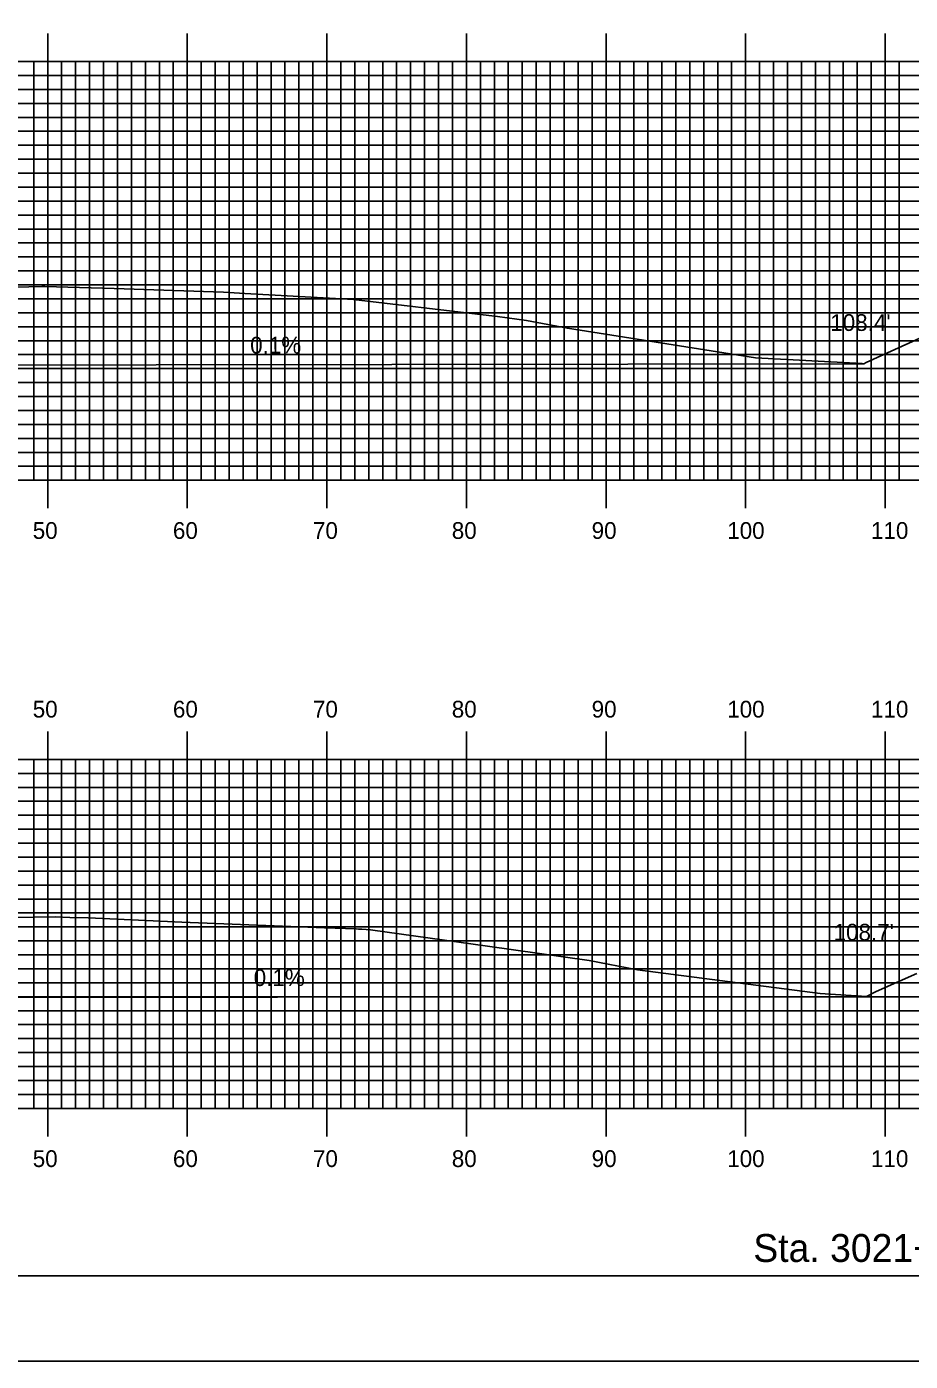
# Model space of a CAD drawing. Extents: x 1686373 to 1686716, y 461260 to 461480.
# Drawn here: x 1686587.3 to 1686650.6, y 461260 to 461355.6 of the extents above; entities that cross this region are included whole.
import ezdxf

# ---------------------------------------------------------------- set-up
doc = ezdxf.new("R2010")
doc.units = 0
for name, color, linetype in [('ANNOTATION', 7, 'Continuous'), ('BORDER', 7, 'Continuous'), ('D_Roadway_SlopeLines', 7, 'Continuous'), ('D_Text_Standard', 7, 'Continuous'), ('H_V ANNOTATION', 7, 'Continuous'), ('M_Roadway_Centerline', 7, 'Continuous'), ('MAJOR', 7, 'Continuous'), ('MINOR', 7, 'Continuous'), ('PLOT BOUNDARY', 7, 'Continuous'), ('S_Roadway_Centerline', 7, 'Continuous')]:
    doc.layers.add(name, color=color, linetype=linetype)

msp = doc.modelspace()

# ---------------------------------------------------------------- linework, layer by layer
at = {"layer": 'BORDER'}
msp.add_lwpolyline([(1686389.169, 461266.072), (1686709.169, 461266.072), (1686709.169, 461476.072), (1686389.169, 461476.072)], close=True, dxfattribs=at)
at = {"layer": 'D_Roadway_SlopeLines'}
for points in [[(1686562.725, 461331.296), (1686647.215, 461331.409)], [(1686562.725, 461331.296), (1686647.215, 461331.409)], [(1686562.725, 461331.296), (1686647.215, 461331.409)], [(1686562.725, 461331.296), (1686647.215, 461331.409)], [(1686563.024, 461285.988), (1686647.42, 461286.094)], [(1686563.024, 461285.988), (1686647.42, 461286.094)], [(1686563.024, 461285.988), (1686647.42, 461286.094)], [(1686563.024, 461285.988), (1686647.42, 461286.094)]]:
    msp.add_lwpolyline(points, dxfattribs=at)
at = {"layer": 'MAJOR'}
for p, q in [((1686588.769, 461355.076), (1686588.769, 461353.072)), ((1686598.769, 461355.076), (1686598.769, 461353.072)), ((1686608.769, 461355.076), (1686608.769, 461353.072)), ((1686618.769, 461355.076), (1686618.769, 461353.072)), ((1686628.769, 461355.076), (1686628.769, 461353.072)), ((1686638.769, 461355.076), (1686638.769, 461353.072)), ((1686648.769, 461355.076), (1686648.769, 461353.072)), ((1686398.769, 461353.072), (1686678.769, 461353.072)), ((1686398.769, 461353.072), (1686678.769, 461353.072)), ((1686588.769, 461323.072), (1686588.769, 461353.072)), ((1686598.769, 461323.072), (1686598.769, 461353.072)), ((1686608.769, 461323.072), (1686608.769, 461353.072)), ((1686618.769, 461323.072), (1686618.769, 461353.072)), ((1686628.769, 461323.072), (1686628.769, 461353.072)), ((1686638.769, 461323.072), (1686638.769, 461353.072)), ((1686648.769, 461323.072), (1686648.769, 461353.072)), ((1686398.769, 461348.072), (1686678.769, 461348.072)), ((1686398.769, 461343.072), (1686678.769, 461343.072)), ((1686398.769, 461338.072), (1686678.769, 461338.072)), ((1686398.769, 461333.072), (1686678.769, 461333.072)), ((1686398.769, 461328.072), (1686678.769, 461328.072)), ((1686398.769, 461323.072), (1686678.769, 461323.072)), ((1686398.769, 461323.072), (1686678.769, 461323.072)), ((1686588.769, 461321.068), (1686588.769, 461323.072)), ((1686598.769, 461321.068), (1686598.769, 461323.072)), ((1686608.769, 461321.068), (1686608.769, 461323.072)), ((1686618.769, 461321.068), (1686618.769, 461323.072)), ((1686628.769, 461321.068), (1686628.769, 461323.072)), ((1686638.769, 461321.068), (1686638.769, 461323.072)), ((1686648.769, 461321.068), (1686648.769, 461323.072)), ((1686588.769, 461305.076), (1686588.769, 461303.072)), ((1686598.769, 461305.076), (1686598.769, 461303.072)), ((1686608.769, 461305.076), (1686608.769, 461303.072)), ((1686618.769, 461305.076), (1686618.769, 461303.072)), ((1686628.769, 461305.076), (1686628.769, 461303.072)), ((1686638.769, 461305.076), (1686638.769, 461303.072)), ((1686648.769, 461305.076), (1686648.769, 461303.072)), ((1686398.769, 461303.072), (1686678.769, 461303.072)), ((1686398.769, 461303.072), (1686678.769, 461303.072)), ((1686588.769, 461278.072), (1686588.769, 461303.072)), ((1686598.769, 461278.072), (1686598.769, 461303.072)), ((1686608.769, 461278.072), (1686608.769, 461303.072)), ((1686618.769, 461278.072), (1686618.769, 461303.072)), ((1686628.769, 461278.072), (1686628.769, 461303.072)), ((1686638.769, 461278.072), (1686638.769, 461303.072)), ((1686648.769, 461278.072), (1686648.769, 461303.072)), ((1686398.769, 461298.072), (1686678.769, 461298.072)), ((1686398.769, 461293.072), (1686678.769, 461293.072)), ((1686398.769, 461288.072), (1686678.769, 461288.072)), ((1686398.769, 461283.072), (1686678.769, 461283.072)), ((1686398.769, 461278.072), (1686678.769, 461278.072)), ((1686398.769, 461278.072), (1686678.769, 461278.072)), ((1686588.769, 461276.068), (1686588.769, 461278.072)), ((1686598.769, 461276.068), (1686598.769, 461278.072)), ((1686608.769, 461276.068), (1686608.769, 461278.072)), ((1686618.769, 461276.068), (1686618.769, 461278.072)), ((1686628.769, 461276.068), (1686628.769, 461278.072)), ((1686638.769, 461276.068), (1686638.769, 461278.072)), ((1686648.769, 461276.068), (1686648.769, 461278.072))]:
    msp.add_line(p, q, dxfattribs=at)
at = {"layer": 'MINOR'}
for p, q in [((1686587.769, 461323.072), (1686587.769, 461353.072)), ((1686589.769, 461323.072), (1686589.769, 461353.072)), ((1686590.769, 461323.072), (1686590.769, 461353.072)), ((1686591.769, 461323.072), (1686591.769, 461353.072)), ((1686592.769, 461323.072), (1686592.769, 461353.072)), ((1686593.769, 461323.072), (1686593.769, 461353.072)), ((1686594.769, 461323.072), (1686594.769, 461353.072)), ((1686595.769, 461323.072), (1686595.769, 461353.072)), ((1686596.769, 461323.072), (1686596.769, 461353.072)), ((1686597.769, 461323.072), (1686597.769, 461353.072)), ((1686599.769, 461323.072), (1686599.769, 461353.072)), ((1686600.769, 461323.072), (1686600.769, 461353.072)), ((1686601.769, 461323.072), (1686601.769, 461353.072)), ((1686602.769, 461323.072), (1686602.769, 461353.072)), ((1686603.769, 461323.072), (1686603.769, 461353.072)), ((1686604.769, 461323.072), (1686604.769, 461353.072)), ((1686605.769, 461323.072), (1686605.769, 461353.072)), ((1686606.769, 461323.072), (1686606.769, 461353.072)), ((1686607.769, 461323.072), (1686607.769, 461353.072)), ((1686609.769, 461323.072), (1686609.769, 461353.072)), ((1686610.769, 461323.072), (1686610.769, 461353.072)), ((1686611.769, 461323.072), (1686611.769, 461353.072)), ((1686612.769, 461323.072), (1686612.769, 461353.072)), ((1686613.769, 461323.072), (1686613.769, 461353.072)), ((1686614.769, 461323.072), (1686614.769, 461353.072)), ((1686615.769, 461323.072), (1686615.769, 461353.072)), ((1686616.769, 461323.072), (1686616.769, 461353.072)), ((1686617.769, 461323.072), (1686617.769, 461353.072)), ((1686619.769, 461323.072), (1686619.769, 461353.072)), ((1686620.769, 461323.072), (1686620.769, 461353.072)), ((1686621.769, 461323.072), (1686621.769, 461353.072)), ((1686622.769, 461323.072), (1686622.769, 461353.072)), ((1686623.769, 461323.072), (1686623.769, 461353.072)), ((1686624.769, 461323.072), (1686624.769, 461353.072)), ((1686625.769, 461323.072), (1686625.769, 461353.072)), ((1686626.769, 461323.072), (1686626.769, 461353.072)), ((1686627.769, 461323.072), (1686627.769, 461353.072)), ((1686629.769, 461323.072), (1686629.769, 461353.072)), ((1686630.769, 461323.072), (1686630.769, 461353.072)), ((1686631.769, 461323.072), (1686631.769, 461353.072)), ((1686632.769, 461323.072), (1686632.769, 461353.072)), ((1686633.769, 461323.072), (1686633.769, 461353.072)), ((1686634.769, 461323.072), (1686634.769, 461353.072)), ((1686635.769, 461323.072), (1686635.769, 461353.072)), ((1686636.769, 461323.072), (1686636.769, 461353.072)), ((1686637.769, 461323.072), (1686637.769, 461353.072)), ((1686639.769, 461323.072), (1686639.769, 461353.072)), ((1686640.769, 461323.072), (1686640.769, 461353.072)), ((1686641.769, 461323.072), (1686641.769, 461353.072)), ((1686642.769, 461323.072), (1686642.769, 461353.072)), ((1686643.769, 461323.072), (1686643.769, 461353.072)), ((1686644.769, 461323.072), (1686644.769, 461353.072)), ((1686645.769, 461323.072), (1686645.769, 461353.072)), ((1686646.769, 461323.072), (1686646.769, 461353.072)), ((1686647.769, 461323.072), (1686647.769, 461353.072)), ((1686649.769, 461323.072), (1686649.769, 461353.072)), ((1686398.769, 461352.072), (1686678.769, 461352.072)), ((1686398.769, 461351.072), (1686678.769, 461351.072)), ((1686398.769, 461350.072), (1686678.769, 461350.072)), ((1686398.769, 461349.072), (1686678.769, 461349.072)), ((1686398.769, 461347.072), (1686678.769, 461347.072)), ((1686398.769, 461346.072), (1686678.769, 461346.072)), ((1686398.769, 461345.072), (1686678.769, 461345.072)), ((1686398.769, 461344.072), (1686678.769, 461344.072)), ((1686398.769, 461342.072), (1686678.769, 461342.072)), ((1686398.769, 461341.072), (1686678.769, 461341.072)), ((1686398.769, 461340.072), (1686678.769, 461340.072)), ((1686398.769, 461339.072), (1686678.769, 461339.072)), ((1686398.769, 461337.072), (1686678.769, 461337.072)), ((1686398.769, 461336.072), (1686678.769, 461336.072)), ((1686398.769, 461335.072), (1686678.769, 461335.072)), ((1686398.769, 461334.072), (1686678.769, 461334.072)), ((1686398.769, 461332.072), (1686678.769, 461332.072)), ((1686398.769, 461331.072), (1686678.769, 461331.072)), ((1686398.769, 461330.072), (1686678.769, 461330.072)), ((1686398.769, 461329.072), (1686678.769, 461329.072)), ((1686398.769, 461327.072), (1686678.769, 461327.072)), ((1686398.769, 461326.072), (1686678.769, 461326.072)), ((1686398.769, 461325.072), (1686678.769, 461325.072)), ((1686398.769, 461324.072), (1686678.769, 461324.072)), ((1686587.769, 461278.072), (1686587.769, 461303.072)), ((1686589.769, 461278.072), (1686589.769, 461303.072)), ((1686590.769, 461278.072), (1686590.769, 461303.072)), ((1686591.769, 461278.072), (1686591.769, 461303.072)), ((1686592.769, 461278.072), (1686592.769, 461303.072)), ((1686593.769, 461278.072), (1686593.769, 461303.072)), ((1686594.769, 461278.072), (1686594.769, 461303.072)), ((1686595.769, 461278.072), (1686595.769, 461303.072)), ((1686596.769, 461278.072), (1686596.769, 461303.072)), ((1686597.769, 461278.072), (1686597.769, 461303.072)), ((1686599.769, 461278.072), (1686599.769, 461303.072)), ((1686600.769, 461278.072), (1686600.769, 461303.072)), ((1686601.769, 461278.072), (1686601.769, 461303.072)), ((1686602.769, 461278.072), (1686602.769, 461303.072)), ((1686603.769, 461278.072), (1686603.769, 461303.072)), ((1686604.769, 461278.072), (1686604.769, 461303.072)), ((1686605.769, 461278.072), (1686605.769, 461303.072)), ((1686606.769, 461278.072), (1686606.769, 461303.072)), ((1686607.769, 461278.072), (1686607.769, 461303.072)), ((1686609.769, 461278.072), (1686609.769, 461303.072)), ((1686610.769, 461278.072), (1686610.769, 461303.072)), ((1686611.769, 461278.072), (1686611.769, 461303.072)), ((1686612.769, 461278.072), (1686612.769, 461303.072)), ((1686613.769, 461278.072), (1686613.769, 461303.072)), ((1686614.769, 461278.072), (1686614.769, 461303.072)), ((1686615.769, 461278.072), (1686615.769, 461303.072)), ((1686616.769, 461278.072), (1686616.769, 461303.072)), ((1686617.769, 461278.072), (1686617.769, 461303.072)), ((1686619.769, 461278.072), (1686619.769, 461303.072)), ((1686620.769, 461278.072), (1686620.769, 461303.072)), ((1686621.769, 461278.072), (1686621.769, 461303.072)), ((1686622.769, 461278.072), (1686622.769, 461303.072)), ((1686623.769, 461278.072), (1686623.769, 461303.072)), ((1686624.769, 461278.072), (1686624.769, 461303.072)), ((1686625.769, 461278.072), (1686625.769, 461303.072)), ((1686626.769, 461278.072), (1686626.769, 461303.072)), ((1686627.769, 461278.072), (1686627.769, 461303.072)), ((1686629.769, 461278.072), (1686629.769, 461303.072)), ((1686630.769, 461278.072), (1686630.769, 461303.072)), ((1686631.769, 461278.072), (1686631.769, 461303.072)), ((1686632.769, 461278.072), (1686632.769, 461303.072)), ((1686633.769, 461278.072), (1686633.769, 461303.072)), ((1686634.769, 461278.072), (1686634.769, 461303.072)), ((1686635.769, 461278.072), (1686635.769, 461303.072)), ((1686636.769, 461278.072), (1686636.769, 461303.072)), ((1686637.769, 461278.072), (1686637.769, 461303.072)), ((1686639.769, 461278.072), (1686639.769, 461303.072)), ((1686640.769, 461278.072), (1686640.769, 461303.072)), ((1686641.769, 461278.072), (1686641.769, 461303.072)), ((1686642.769, 461278.072), (1686642.769, 461303.072)), ((1686643.769, 461278.072), (1686643.769, 461303.072)), ((1686644.769, 461278.072), (1686644.769, 461303.072)), ((1686645.769, 461278.072), (1686645.769, 461303.072)), ((1686646.769, 461278.072), (1686646.769, 461303.072)), ((1686647.769, 461278.072), (1686647.769, 461303.072)), ((1686649.769, 461278.072), (1686649.769, 461303.072)), ((1686398.769, 461302.072), (1686678.769, 461302.072)), ((1686398.769, 461301.072), (1686678.769, 461301.072)), ((1686398.769, 461300.072), (1686678.769, 461300.072)), ((1686398.769, 461299.072), (1686678.769, 461299.072)), ((1686398.769, 461297.072), (1686678.769, 461297.072)), ((1686398.769, 461296.072), (1686678.769, 461296.072)), ((1686398.769, 461295.072), (1686678.769, 461295.072)), ((1686398.769, 461294.072), (1686678.769, 461294.072)), ((1686398.769, 461292.072), (1686678.769, 461292.072)), ((1686398.769, 461291.072), (1686678.769, 461291.072)), ((1686398.769, 461290.072), (1686678.769, 461290.072)), ((1686398.769, 461289.072), (1686678.769, 461289.072)), ((1686398.769, 461287.072), (1686678.769, 461287.072)), ((1686398.769, 461286.072), (1686678.769, 461286.072)), ((1686398.769, 461285.072), (1686678.769, 461285.072)), ((1686398.769, 461284.072), (1686678.769, 461284.072)), ((1686398.769, 461282.072), (1686678.769, 461282.072)), ((1686398.769, 461281.072), (1686678.769, 461281.072)), ((1686398.769, 461280.072), (1686678.769, 461280.072)), ((1686398.769, 461279.072), (1686678.769, 461279.072))]:
    msp.add_line(p, q, dxfattribs=at)
at = {"layer": 'PLOT BOUNDARY'}
msp.add_lwpolyline([(1686372.982, 461259.954), (1686712.982, 461259.954), (1686712.982, 461479.954), (1686372.982, 461479.954)], close=True, dxfattribs=at)
at = {"layer": 'S_Roadway_Centerline'}
for points in [[(1686584.545, 461336.87), (1686587.425, 461336.941), (1686588.352, 461336.954), (1686588.564, 461336.943), (1686593.536, 461336.819), (1686601.357, 461336.551), (1686602.902, 461336.447), (1686610.676, 461336.015), (1686619.978, 461334.924), (1686620.995, 461334.815), (1686623.068, 461334.522), (1686626.002, 461333.959), (1686639.467, 461331.843), (1686647.13, 461331.426), (1686647.238, 461331.419), (1686647.242, 461331.421), (1686647.415, 461331.5), (1686668.412, 461341.037)], [(1686584.784, 461291.736), (1686589.323, 461291.802), (1686590.358, 461291.751), (1686591.67, 461291.719), (1686598.391, 461291.425), (1686608.608, 461291.016), (1686610.871, 461290.93), (1686611.038, 461290.919), (1686611.123, 461290.913), (1686611.273, 461290.902), (1686611.89, 461290.853), (1686620.27, 461289.698), (1686627.573, 461288.666), (1686631.02, 461288.005), (1686644.107, 461286.311), (1686647.42, 461286.094), (1686648.131, 461286.436), (1686651.024, 461287.732)]]:
    msp.add_lwpolyline(points, dxfattribs=at)

# ---------------------------------------------------------------- texts
at = {"layer": 'ANNOTATION'}
for rotation, p in [(0.07693, (1686603.277, 461332.15)), (0.07174, (1686603.529, 461286.839))]:
    msp.add_text('0.1%', height=1.2, rotation=rotation, dxfattribs=at).set_placement(p)
at = {"layer": 'D_Text_Standard'}
for s, p in [("108.4'", (1686644.834, 461333.769)), ("108.7'", (1686645.071, 461290.094))]:
    msp.add_text(s, height=1.2, dxfattribs=at).set_placement(p)
at = {"layer": 'H_V ANNOTATION'}
for s, height, p in [('50', 1.2, (1686587.698, 461318.872)), ('60', 1.2, (1686597.741, 461318.872)), ('70', 1.2, (1686607.773, 461318.872)), ('80', 1.2, (1686617.719, 461318.872)), ('90', 1.2, (1686627.741, 461318.872)), ('100', 1.2, (1686637.452, 461318.872)), ('110', 1.2, (1686647.752, 461318.872)), ('50', 1.2, (1686587.698, 461306.072)), ('60', 1.2, (1686597.741, 461306.072)), ('70', 1.2, (1686607.773, 461306.072)), ('80', 1.2, (1686617.719, 461306.072)), ('90', 1.2, (1686627.741, 461306.072)), ('100', 1.2, (1686637.452, 461306.072)), ('110', 1.2, (1686647.752, 461306.072)), ('50', 1.2, (1686587.698, 461273.872)), ('60', 1.2, (1686597.741, 461273.872)), ('70', 1.2, (1686607.773, 461273.872)), ('80', 1.2, (1686617.719, 461273.872)), ('90', 1.2, (1686627.741, 461273.872)), ('100', 1.2, (1686637.452, 461273.872)), ('110', 1.2, (1686647.752, 461273.872)), ('Sta. 3021+00.00 to Sta. 3021+17.16', 2.0004, (1686639.321, 461267.072))]:
    msp.add_text(s, height=height, dxfattribs=at).set_placement(p)
at = {"layer": 'M_Roadway_Centerline'}
for s, p in [('C', (1686588.347, 461336.954)), ('L', (1686588.352, 461336.947)), ('C', (1686589.317, 461291.802)), ('L', (1686589.323, 461291.794))]:
    msp.add_text(s, height=0.0146, dxfattribs=at).set_placement(p)

doc.saveas('drawing.dxf')
